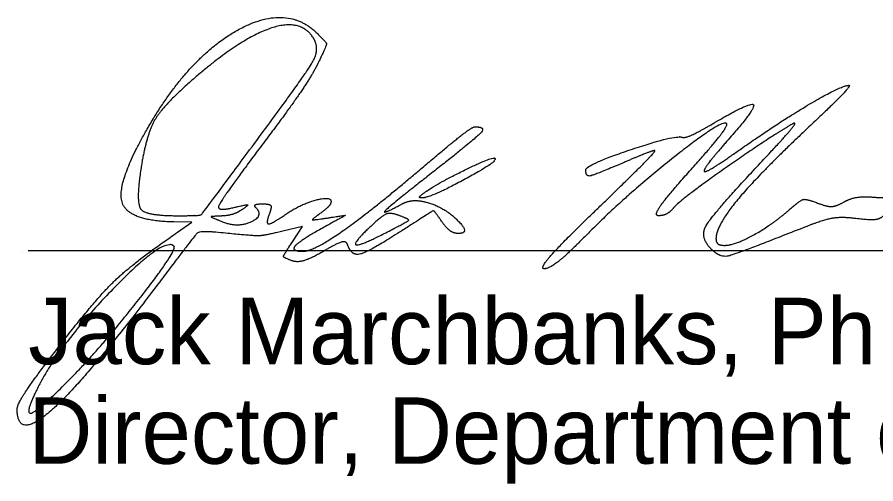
# Model space of a CAD drawing. Extents: x 0 to 45, y -99 to 22.
# Drawn here: x 24.965 to 26.778, y 7.065 to 8.049 of the extents above; entities that cross this region are included whole.
import ezdxf

# ---------------------------------------------------------------- set-up
doc = ezdxf.new("R2010")
doc.units = 0
doc.layers.add('SH_Cut_Line', color=7, linetype='Continuous')
doc.layers.add('SH_Text', color=7, linetype='Continuous')

msp = doc.modelspace()

# ---------------------------------------------------------------- linework, layer by layer
at = {"layer": 'SH_Cut_Line'}
msp.add_line((24.9887, 7.5573), (28.4887, 7.5573), dxfattribs=at)
at = {"layer": 'SH_Text'}
for p, q in [((25.451, 7.7623), (25.451, 7.7623)), ((25.8164, 7.6725), (25.8164, 7.6725)), ((25.7716, 7.6308), (25.7716, 7.6308)), ((26.1882, 7.6434), (26.1882, 7.6434)), ((24.9766, 7.5555), (24.9766, 7.5555))]:
    msp.add_line(p, q, dxfattribs=at)
for points in [[(25.3034, 7.5954), (25.3341, 7.6166), (25.2962, 7.6173)], [(25.5463, 7.5755), (25.5675, 7.6079), (25.5258, 7.5978)]]:
    msp.add_lwpolyline(points, dxfattribs=at)
for points in [[(25.2397, 7.8131), (25.326, 7.9635), (25.5341, 8.0795), (25.5998, 8.0138)], [(25.5908, 8.0047), (25.5648, 8.0467), (25.4387, 8.0055), (25.3434, 7.9239)], [(25.5998, 8.0138), (25.6185, 7.9951), (25.6186, 7.99), (25.6002, 7.9516)], [(25.451, 7.7623), (25.5724, 7.9258), (25.6048, 7.982), (25.5908, 8.0047)], [(25.6002, 7.9516), (25.5893, 7.9286), (25.5376, 7.853), (25.4853, 7.7837)], [(25.3434, 7.9239), (25.2767, 7.8668), (25.2379, 7.8027), (25.2268, 7.7315)], [(26.4934, 7.7716), (26.574, 7.8282), (26.7053, 7.9054), (26.721, 7.9054)], [(26.721, 7.9054), (26.7259, 7.9054), (26.6846, 7.8628), (26.6292, 7.8107)], [(26.4345, 7.8251), (26.5132, 7.8712), (26.5255, 7.858), (26.4662, 7.7907)], [(25.2962, 7.6173), (25.1983, 7.619), (25.1749, 7.7001), (25.2397, 7.8131)], [(25.8298, 7.7396), (25.8803, 7.7825), (25.9258, 7.8176), (25.9309, 7.8177)], [(25.9309, 7.8177), (25.9558, 7.8182), (25.9324, 7.7927), (25.8466, 7.7254)], [(26.4626, 7.8248), (26.453, 7.8344), (26.2432, 7.6675), (26.1653, 7.5882)], [(26.6028, 7.8244), (26.5538, 7.7966), (26.3654, 7.6644), (26.3522, 7.6484)], [(26.3689, 7.7959), (26.3744, 7.794), (26.4039, 7.8072), (26.4345, 7.8251)], [(26.3847, 7.7245), (26.431, 7.7762), (26.4661, 7.8213), (26.4626, 7.8248)], [(26.5376, 7.7454), (26.5838, 7.7947), (26.6131, 7.8302), (26.6028, 7.8244)], [(26.1655, 7.7273), (26.1657, 7.7378), (26.3531, 7.801), (26.3689, 7.7959)], [(26.6292, 7.8107), (26.5296, 7.717), (26.4403, 7.6088), (26.4403, 7.5819)], [(25.4853, 7.7837), (25.4331, 7.7143), (25.3903, 7.6537), (25.3903, 7.6489)], [(26.4662, 7.7907), (26.4382, 7.7589), (26.4153, 7.7292), (26.4153, 7.7247)], [(26.7727, 7.6696), (26.8062, 7.6668), (26.8297, 7.6832), (26.9477, 7.792)], [(25.3049, 7.6304), (25.3516, 7.6304), (25.3561, 7.6345), (25.451, 7.7623)], [(26.1882, 7.6434), (26.2592, 7.7119), (26.3145, 7.7679), (26.3111, 7.7679)], [(26.3111, 7.7679), (26.3077, 7.7679), (26.2786, 7.7567), (26.2466, 7.7429)], [(26.4153, 7.7247), (26.4153, 7.7203), (26.4505, 7.7414), (26.4934, 7.7716)], [(25.5685, 7.5554), (25.5916, 7.5554), (25.7176, 7.6442), (25.8298, 7.7396)], [(25.8164, 7.6725), (25.8368, 7.6903), (25.9688, 7.7561), (25.9739, 7.751)], [(25.9739, 7.751), (25.9801, 7.7448), (25.8375, 7.6679), (25.8198, 7.6679)], [(26.2466, 7.7429), (26.184, 7.7161), (26.1652, 7.7125), (26.1655, 7.7273)], [(26.4306, 7.5598), (26.4053, 7.585), (26.4343, 7.6351), (26.5376, 7.7454)], [(25.2268, 7.7315), (25.2154, 7.6581), (25.2368, 7.6304), (25.3049, 7.6304)], [(25.8466, 7.7254), (25.7533, 7.6524), (25.7319, 7.6308), (25.7758, 7.6543)], [(26.3189, 7.6304), (26.3086, 7.6304), (26.3375, 7.6717), (26.3847, 7.7245)], [(25.5344, 7.6348), (25.5633, 7.6546), (25.6278, 7.6721), (25.6278, 7.6602)], [(25.8198, 7.6679), (25.8151, 7.6679), (25.8135, 7.67), (25.8164, 7.6725)], [(26.7097, 7.6591), (26.7231, 7.6667), (26.7515, 7.6714), (26.7727, 7.6696)], [(25.3903, 7.6489), (25.3903, 7.6441), (25.4058, 7.6438), (25.4247, 7.6482)], [(25.4247, 7.6482), (25.4502, 7.6541), (25.4542, 7.6529), (25.4403, 7.6435)], [(25.4694, 7.6472), (25.4649, 7.6517), (25.4711, 7.6554), (25.4833, 7.6554)], [(25.4833, 7.6554), (25.4979, 7.6554), (25.503, 7.649), (25.4983, 7.6367)], [(25.6278, 7.6602), (25.6278, 7.6556), (25.6181, 7.6448), (25.6062, 7.6361)], [(25.7758, 7.6543), (25.7884, 7.6611), (25.8123, 7.6632), (25.8289, 7.659)], [(25.8289, 7.659), (25.865, 7.6498), (25.9234, 7.5929), (25.8967, 7.5929)], [(26.3522, 7.6484), (26.344, 7.6385), (26.329, 7.6304), (26.3189, 7.6304)], [(26.5978, 7.6454), (26.6181, 7.6635), (26.631, 7.6661), (26.6547, 7.6571)], [(26.6547, 7.6571), (26.6749, 7.6494), (26.6937, 7.6501), (26.7097, 7.6591)], [(25.4403, 7.6435), (25.43, 7.6365), (25.4103, 7.6304), (25.3966, 7.6298)], [(25.4007, 7.6171), (25.4306, 7.6052), (25.4868, 7.6297), (25.4694, 7.6472)], [(25.4983, 7.6367), (25.4894, 7.6134), (25.5022, 7.6127), (25.5344, 7.6348)], [(25.6062, 7.6361), (25.5873, 7.6223), (25.5893, 7.621), (25.6218, 7.6259)], [(25.6218, 7.6259), (25.6586, 7.6315), (25.6585, 7.6312), (25.613, 7.6061)], [(25.7716, 7.6308), (25.7543, 7.6372), (25.7378, 7.632), (25.7184, 7.6143)], [(25.7434, 7.5945), (25.7898, 7.6182), (25.7934, 7.6228), (25.7716, 7.6308)], [(25.862, 7.6176), (25.8451, 7.6417), (25.8431, 7.6412), (25.7773, 7.5988)], [(26.0778, 7.5186), (26.0675, 7.5188), (26.1172, 7.575), (26.1882, 7.6434)], [(26.4584, 7.5679), (26.4801, 7.5679), (26.5614, 7.6131), (26.5978, 7.6454)], [(26.8052, 7.6389), (26.7896, 7.6247), (26.7683, 7.6203), (26.7357, 7.6244)], [(25.3966, 7.6298), (25.3742, 7.6289), (25.3746, 7.6276), (25.4007, 7.6171)], [(25.7184, 7.6143), (25.6742, 7.5738), (25.6854, 7.5649), (25.7434, 7.5945)], [(25.8967, 7.5929), (25.8871, 7.5929), (25.8715, 7.604), (25.862, 7.6176)], [(26.7357, 7.6244), (26.7065, 7.6282), (26.6667, 7.6217), (26.6302, 7.6073)], [(25.0524, 7.3532), (25.1301, 7.4537), (25.2102, 7.531), (25.3034, 7.5954)], [(25.3846, 7.5955), (25.3512, 7.5988), (25.3394, 7.5883), (25.2628, 7.4867)], [(25.5258, 7.5978), (25.4854, 7.5881), (25.4631, 7.5877), (25.3846, 7.5955)], [(25.613, 7.6061), (25.5619, 7.5779), (25.5422, 7.5554), (25.5685, 7.5554)], [(25.7773, 7.5988), (25.7084, 7.5545), (25.671, 7.5447), (25.6628, 7.5691)], [(26.6302, 7.6073), (26.4841, 7.5496), (26.4491, 7.5413), (26.4306, 7.5598)], [(25.6628, 7.5691), (25.66, 7.5776), (25.6408, 7.5725), (25.6117, 7.5553)], [(26.1653, 7.5882), (26.1275, 7.5498), (26.0881, 7.5184), (26.0778, 7.5186)], [(26.4403, 7.5819), (26.4403, 7.5742), (26.4484, 7.5679), (26.4584, 7.5679)], [(25.2962, 7.5662), (25.2753, 7.5871), (25.0568, 7.3614), (25.0105, 7.271)], [(25.0806, 7.2898), (25.1482, 7.3589), (25.3039, 7.5585), (25.2962, 7.5662)], [(25.5451, 7.5355), (25.5269, 7.5425), (25.527, 7.5461), (25.5463, 7.5755)], [(25.6117, 7.5553), (25.5861, 7.5402), (25.5561, 7.5313), (25.5451, 7.5355)], [(25.2628, 7.4867), (25.1104, 7.2846), (24.9653, 7.1559), (24.9653, 7.2229)], [(24.9653, 7.2229), (24.9653, 7.2326), (25.0045, 7.2912), (25.0524, 7.3532)], [(25.0105, 7.271), (24.9793, 7.2101), (25.0109, 7.2185), (25.0806, 7.2898)]]:
    msp.add_open_spline(points, degree=2, dxfattribs=at)

# ---------------------------------------------------------------- texts
for s, p in [('Jack Marchbanks, PhD', (24.9887, 7.3173)), ('Director, Department of Transportation', (24.9887, 7.1073))]:
    msp.add_text(s, height=0.14, dxfattribs=at).set_placement(p)

doc.saveas('drawing.dxf')
